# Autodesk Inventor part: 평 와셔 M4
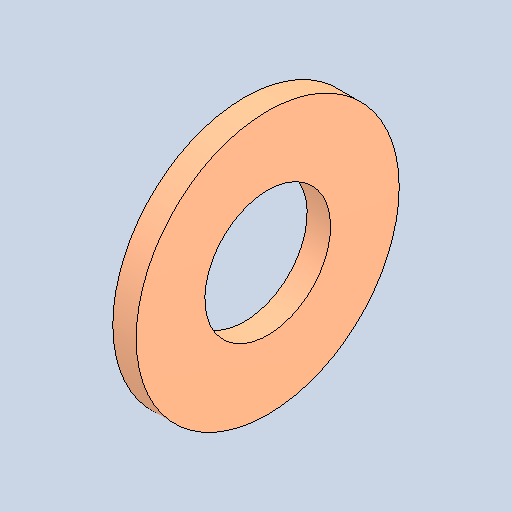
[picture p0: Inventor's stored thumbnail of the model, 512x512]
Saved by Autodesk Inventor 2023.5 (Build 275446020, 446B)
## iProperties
Created: 2026-07
Part Number: 평 와셔 M4
Material: 강철, 연강
Description: 평면 와셔
Document SubType Name: Modeling
Designer: 1강의실14
Density: 7.85 g/cm^3
Appearance: 기본값
Author: jhkim
Sending System: Autodesk Inventor 2027
Preprocessor: ST-DEVELOPER v20.1
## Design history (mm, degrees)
node "평 와셔 M41"
node "솔리드1"
body "Solid1"
